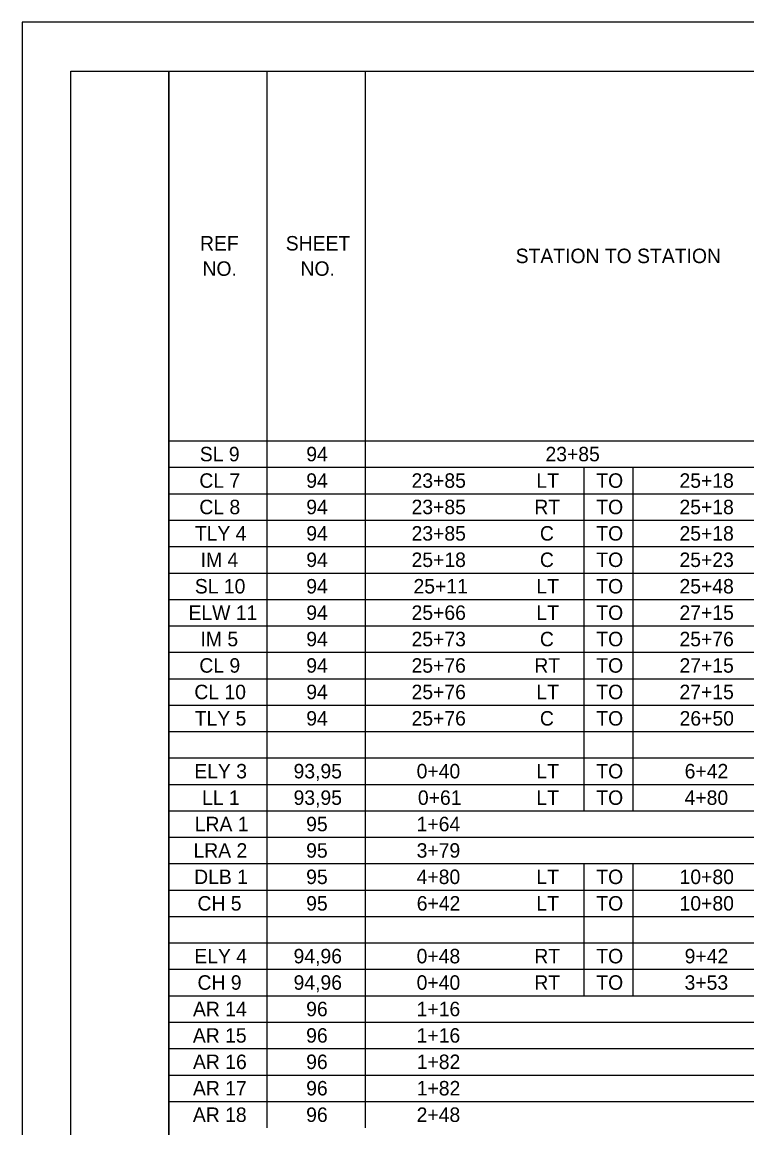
# Model space of a CAD drawing. Extents: x 0 to 34, y 0 to 22.
# Drawn here: x 0 to 7.41, y 10.69 to 22 of the extents above; entities that cross this region are included whole.
import ezdxf

# ---------------------------------------------------------------- set-up
doc = ezdxf.new("R2010")
doc.units = 0
for name, color, linetype in [('SH_Border', 7, 'Continuous'), ('SH_Cut_Line', 7, 'Continuous'), ('SH_Data', 7, 'Continuous')]:
    doc.layers.add(name, color=color, linetype=linetype)

msp = doc.modelspace()

# ---------------------------------------------------------------- linework, layer by layer
at = {"layer": 'SH_Border'}
for points in [[(0.5, 21.5), (1.5, 21.5), (1.5, 0.5), (0.5, 0.5)], [(1.5, 21.5), (33.5, 21.5), (33.5, 0.5), (1.5, 0.5)]]:
    msp.add_lwpolyline(points, close=True, dxfattribs=at)
at = {"layer": 'SH_Cut_Line'}
msp.add_lwpolyline([(0, 0), (34, 0), (34, 22), (0, 22)], close=True, dxfattribs=at)
at = {"layer": 'SH_Data'}
for p, q in [((1.5, 21.5), (5.747, 21.5)), ((1.5, 21.5), (1.5, 21.23)), ((2.504, 21.5), (2.504, 21.23)), ((3.508, 21.5), (3.508, 21.23)), ((5.747, 21.5), (6.249, 21.5)), ((6.249, 21.5), (7.716, 21.5)), ((1.5, 21.23), (1.5, 20.96)), ((2.504, 21.23), (2.504, 20.96)), ((3.508, 21.23), (3.508, 20.96)), ((1.5, 20.96), (1.5, 20.69)), ((2.504, 20.96), (2.504, 20.69)), ((3.508, 20.96), (3.508, 20.69)), ((1.5, 20.69), (1.5, 20.419)), ((2.504, 20.69), (2.504, 20.419)), ((3.508, 20.69), (3.508, 20.419)), ((1.5, 20.419), (1.5, 20.149)), ((2.504, 20.419), (2.504, 20.149)), ((3.508, 20.419), (3.508, 20.149)), ((1.5, 20.149), (1.5, 19.879)), ((2.504, 20.149), (2.504, 19.879)), ((3.508, 20.149), (3.508, 19.879)), ((1.5, 19.879), (1.5, 19.609)), ((2.504, 19.879), (2.504, 19.609)), ((3.508, 19.879), (3.508, 19.609)), ((1.5, 19.609), (1.5, 19.338)), ((2.504, 19.609), (2.504, 19.338)), ((3.508, 19.609), (3.508, 19.338)), ((1.5, 19.338), (1.5, 19.068)), ((2.504, 19.338), (2.504, 19.068)), ((3.508, 19.338), (3.508, 19.068)), ((1.5, 19.068), (1.5, 18.798)), ((2.504, 19.068), (2.504, 18.798)), ((3.508, 19.068), (3.508, 18.798)), ((1.5, 18.798), (1.5, 18.528)), ((2.504, 18.798), (2.504, 18.528)), ((3.508, 18.798), (3.508, 18.528)), ((1.5, 18.528), (1.5, 18.257)), ((2.504, 18.528), (2.504, 18.257)), ((3.508, 18.528), (3.508, 18.257)), ((1.5, 18.257), (1.5, 17.987)), ((2.504, 18.257), (2.504, 17.987)), ((3.508, 18.257), (3.508, 17.987)), ((1.5, 17.987), (1.5, 17.717)), ((2.504, 17.987), (2.504, 17.717)), ((3.508, 17.987), (3.508, 17.717)), ((1.5, 17.717), (5.747, 17.717)), ((1.5, 17.717), (1.5, 17.447)), ((2.504, 17.717), (2.504, 17.447)), ((3.508, 17.717), (3.508, 17.447)), ((5.747, 17.717), (6.249, 17.717)), ((6.249, 17.717), (7.716, 17.717)), ((1.5, 17.447), (5.747, 17.447)), ((1.5, 17.447), (1.5, 17.176)), ((2.504, 17.447), (2.504, 17.176)), ((3.508, 17.447), (3.508, 17.176)), ((5.747, 17.447), (6.249, 17.447)), ((5.747, 17.447), (5.747, 17.176)), ((6.249, 17.447), (7.716, 17.447)), ((6.249, 17.447), (6.249, 17.176)), ((1.5, 17.176), (5.747, 17.176)), ((1.5, 17.176), (1.5, 16.906)), ((2.504, 17.176), (2.504, 16.906)), ((3.508, 17.176), (3.508, 16.906)), ((5.747, 17.176), (6.249, 17.176)), ((5.747, 17.176), (5.747, 16.906)), ((6.249, 17.176), (7.716, 17.176)), ((6.249, 17.176), (6.249, 16.906)), ((1.5, 16.906), (5.747, 16.906)), ((1.5, 16.906), (1.5, 16.636)), ((2.504, 16.906), (2.504, 16.636)), ((3.508, 16.906), (3.508, 16.636)), ((5.747, 16.906), (6.249, 16.906)), ((5.747, 16.906), (5.747, 16.636)), ((6.249, 16.906), (7.716, 16.906)), ((6.249, 16.906), (6.249, 16.636)), ((1.5, 16.636), (5.747, 16.636)), ((1.5, 16.636), (1.5, 16.365)), ((2.504, 16.636), (2.504, 16.365)), ((3.508, 16.636), (3.508, 16.365)), ((5.747, 16.636), (6.249, 16.636)), ((5.747, 16.636), (5.747, 16.365)), ((6.249, 16.636), (7.716, 16.636)), ((6.249, 16.636), (6.249, 16.365)), ((1.5, 16.365), (5.747, 16.365)), ((1.5, 16.365), (1.5, 16.095)), ((2.504, 16.365), (2.504, 16.095)), ((3.508, 16.365), (3.508, 16.095)), ((5.747, 16.365), (6.249, 16.365)), ((5.747, 16.365), (5.747, 16.095)), ((6.249, 16.365), (7.716, 16.365)), ((6.249, 16.365), (6.249, 16.095)), ((1.5, 16.095), (5.747, 16.095)), ((1.5, 16.095), (1.5, 15.825)), ((2.504, 16.095), (2.504, 15.825)), ((3.508, 16.095), (3.508, 15.825)), ((5.747, 16.095), (6.249, 16.095)), ((5.747, 16.095), (5.747, 15.825)), ((6.249, 16.095), (7.716, 16.095)), ((6.249, 16.095), (6.249, 15.825)), ((1.5, 15.825), (5.747, 15.825)), ((1.5, 15.825), (1.5, 15.555)), ((2.504, 15.825), (2.504, 15.555)), ((3.508, 15.825), (3.508, 15.555)), ((5.747, 15.825), (6.249, 15.825)), ((5.747, 15.825), (5.747, 15.555)), ((6.249, 15.825), (7.716, 15.825)), ((6.249, 15.825), (6.249, 15.555)), ((1.5, 15.555), (5.747, 15.555)), ((1.5, 15.555), (1.5, 15.284)), ((2.504, 15.555), (2.504, 15.284)), ((3.508, 15.555), (3.508, 15.284)), ((5.747, 15.555), (6.249, 15.555)), ((5.747, 15.555), (5.747, 15.284)), ((6.249, 15.555), (7.716, 15.555)), ((6.249, 15.555), (6.249, 15.284)), ((1.5, 15.284), (5.747, 15.284)), ((1.5, 15.284), (1.5, 15.014)), ((2.504, 15.284), (2.504, 15.014)), ((3.508, 15.284), (3.508, 15.014)), ((5.747, 15.284), (6.249, 15.284)), ((5.747, 15.284), (5.747, 15.014)), ((6.249, 15.284), (7.716, 15.284)), ((6.249, 15.284), (6.249, 15.014)), ((1.5, 15.014), (5.747, 15.014)), ((1.5, 15.014), (1.5, 14.744)), ((2.504, 15.014), (2.504, 14.744)), ((3.508, 15.014), (3.508, 14.744)), ((5.747, 15.014), (6.249, 15.014)), ((5.747, 15.014), (5.747, 14.744)), ((6.249, 15.014), (7.716, 15.014)), ((6.249, 15.014), (6.249, 14.744)), ((1.5, 14.744), (5.747, 14.744)), ((1.5, 14.744), (1.5, 14.474)), ((2.504, 14.744), (2.504, 14.474)), ((3.508, 14.744), (3.508, 14.474)), ((5.747, 14.744), (6.249, 14.744)), ((5.747, 14.744), (5.747, 14.474)), ((6.249, 14.744), (7.716, 14.744)), ((6.249, 14.744), (6.249, 14.474)), ((1.5, 14.474), (5.747, 14.474)), ((1.5, 14.474), (1.5, 14.203)), ((2.504, 14.474), (2.504, 14.203)), ((3.508, 14.474), (3.508, 14.203)), ((5.747, 14.474), (6.249, 14.474)), ((5.747, 14.474), (5.747, 14.203)), ((6.249, 14.474), (7.716, 14.474)), ((6.249, 14.474), (6.249, 14.203)), ((1.5, 14.203), (5.747, 14.203)), ((1.5, 14.203), (1.5, 13.933)), ((2.504, 14.203), (2.504, 13.933)), ((3.508, 14.203), (3.508, 13.933)), ((5.747, 14.203), (6.249, 14.203)), ((5.747, 14.203), (5.747, 13.933)), ((6.249, 14.203), (7.716, 14.203)), ((6.249, 14.203), (6.249, 13.933)), ((1.5, 13.933), (5.747, 13.933)), ((1.5, 13.933), (1.5, 13.663)), ((2.504, 13.933), (2.504, 13.663)), ((3.508, 13.933), (3.508, 13.663)), ((5.747, 13.933), (6.249, 13.933)), ((6.249, 13.933), (7.716, 13.933)), ((1.5, 13.663), (5.747, 13.663)), ((1.5, 13.663), (1.5, 13.393)), ((2.504, 13.663), (2.504, 13.393)), ((3.508, 13.663), (3.508, 13.393)), ((5.747, 13.663), (6.249, 13.663)), ((6.249, 13.663), (7.716, 13.663)), ((1.5, 13.393), (5.747, 13.393)), ((1.5, 13.393), (1.5, 13.122)), ((2.504, 13.393), (2.504, 13.122)), ((3.508, 13.393), (3.508, 13.122)), ((5.747, 13.393), (6.249, 13.393)), ((5.747, 13.393), (5.747, 13.122)), ((6.249, 13.393), (7.716, 13.393)), ((6.249, 13.393), (6.249, 13.122)), ((1.5, 13.122), (5.747, 13.122)), ((1.5, 13.122), (1.5, 12.852)), ((2.504, 13.122), (2.504, 12.852)), ((3.508, 13.122), (3.508, 12.852)), ((5.747, 13.122), (6.249, 13.122)), ((5.747, 13.122), (5.747, 12.852)), ((6.249, 13.122), (7.716, 13.122)), ((6.249, 13.122), (6.249, 12.852)), ((1.5, 12.852), (5.747, 12.852)), ((1.5, 12.852), (1.5, 12.582)), ((2.504, 12.852), (2.504, 12.582)), ((3.508, 12.852), (3.508, 12.582)), ((5.747, 12.852), (6.249, 12.852)), ((5.747, 12.852), (5.747, 12.582)), ((6.249, 12.852), (7.716, 12.852)), ((6.249, 12.852), (6.249, 12.582)), ((1.5, 12.582), (5.747, 12.582)), ((1.5, 12.582), (1.5, 12.312)), ((2.504, 12.582), (2.504, 12.312)), ((3.508, 12.582), (3.508, 12.312)), ((5.747, 12.582), (6.249, 12.582)), ((5.747, 12.582), (5.747, 12.312)), ((6.249, 12.582), (7.716, 12.582)), ((6.249, 12.582), (6.249, 12.312)), ((1.5, 12.312), (5.747, 12.312)), ((1.5, 12.312), (1.5, 12.041)), ((2.504, 12.312), (2.504, 12.041)), ((3.508, 12.312), (3.508, 12.041)), ((5.747, 12.312), (6.249, 12.312)), ((5.747, 12.312), (5.747, 12.041)), ((6.249, 12.312), (7.716, 12.312)), ((6.249, 12.312), (6.249, 12.041)), ((1.5, 12.041), (5.747, 12.041)), ((1.5, 12.041), (1.5, 11.771)), ((2.504, 12.041), (2.504, 11.771)), ((3.508, 12.041), (3.508, 11.771)), ((5.747, 12.041), (6.249, 12.041)), ((6.249, 12.041), (7.716, 12.041)), ((1.5, 11.771), (5.747, 11.771)), ((1.5, 11.771), (1.5, 11.501)), ((2.504, 11.771), (2.504, 11.501)), ((3.508, 11.771), (3.508, 11.501)), ((5.747, 11.771), (6.249, 11.771)), ((6.249, 11.771), (7.716, 11.771)), ((1.5, 11.501), (5.747, 11.501)), ((1.5, 11.501), (1.5, 11.231)), ((2.504, 11.501), (2.504, 11.231)), ((3.508, 11.501), (3.508, 11.231)), ((5.747, 11.501), (6.249, 11.501)), ((6.249, 11.501), (7.716, 11.501)), ((1.5, 11.231), (5.747, 11.231)), ((1.5, 11.231), (1.5, 10.96)), ((2.504, 11.231), (2.504, 10.96)), ((3.508, 11.231), (3.508, 10.96)), ((5.747, 11.231), (6.249, 11.231)), ((6.249, 11.231), (7.716, 11.231)), ((1.5, 10.96), (5.747, 10.96)), ((1.5, 10.96), (1.5, 10.69)), ((2.504, 10.96), (2.504, 10.69)), ((3.508, 10.96), (3.508, 10.69)), ((5.747, 10.96), (6.249, 10.96)), ((6.249, 10.96), (7.716, 10.96))]:
    msp.add_line(p, q, dxfattribs=at)

# ---------------------------------------------------------------- texts
for s, p in [('REF', (1.82, 19.664)), ('SHEET', (2.697, 19.664)), ('STATION TO STATION', (5.049, 19.535)), ('NO.', (1.845, 19.405)), ('NO.', (2.848, 19.405)), ('SL 9', (1.818, 17.508)), ('94', (2.907, 17.508)), ('23+85', (5.354, 17.508)), ('CL 7', (1.813, 17.237)), ('94', (2.907, 17.237)), ('23+85', (3.984, 17.237)), ('LT', (5.261, 17.237)), ('TO', (5.874, 17.237)), ('25+18', (6.725, 17.237)), ('CL 8', (1.813, 16.967)), ('94', (2.907, 16.967)), ('23+85', (3.984, 16.967)), ('RT', (5.24, 16.967)), ('TO', (5.874, 16.967)), ('25+18', (6.725, 16.967)), ('TLY 4', (1.767, 16.697)), ('94', (2.907, 16.697)), ('23+85', (3.984, 16.697)), ('C', (5.297, 16.697)), ('TO', (5.874, 16.697)), ('25+18', (6.725, 16.697)), ('IM 4', (1.826, 16.427)), ('94', (2.907, 16.427)), ('25+18', (3.984, 16.427)), ('C', (5.297, 16.427)), ('TO', (5.874, 16.427)), ('25+23', (6.725, 16.427)), ('SL 10', (1.767, 16.156)), ('94', (2.907, 16.156)), ('25+11', (4.004, 16.156)), ('LT', (5.261, 16.156)), ('TO', (5.874, 16.156)), ('25+48', (6.725, 16.156)), ('ELW 11', (1.702, 15.886)), ('94', (2.907, 15.886)), ('25+66', (3.984, 15.886)), ('LT', (5.261, 15.886)), ('TO', (5.874, 15.886)), ('27+15', (6.725, 15.886)), ('IM 5', (1.825, 15.616)), ('94', (2.907, 15.616)), ('25+73', (3.984, 15.616)), ('C', (5.297, 15.616)), ('TO', (5.874, 15.616)), ('25+76', (6.725, 15.616)), ('CL 9', (1.813, 15.346)), ('94', (2.907, 15.346)), ('25+76', (3.984, 15.346)), ('TO', (5.874, 15.346)), ('27+15', (6.725, 15.346)), ('RT', (5.24, 15.346)), ('CL 10', (1.762, 15.075)), ('94', (2.907, 15.075)), ('25+76', (3.984, 15.075)), ('LT', (5.261, 15.075)), ('TO', (5.874, 15.075)), ('27+15', (6.725, 15.075)), ('TLY 5', (1.766, 14.805)), ('94', (2.907, 14.805)), ('25+76', (3.984, 14.805)), ('C', (5.297, 14.805)), ('TO', (5.874, 14.805)), ('26+50', (6.726, 14.805)), ('ELY 3', (1.761, 14.265)), ('93,95', (2.777, 14.265)), ('0+40', (4.036, 14.265)), ('LT', (5.261, 14.265)), ('TO', (5.874, 14.265)), ('6+42', (6.778, 14.265)), ('LL 1', (1.841, 13.994)), ('93,95', (2.777, 13.994)), ('0+61', (4.049, 13.994)), ('LT', (5.261, 13.994)), ('TO', (5.874, 13.994)), ('4+80', (6.777, 13.994)), ('LRA 1', (1.766, 13.724)), ('95', (2.906, 13.724)), ('1+64', (4.036, 13.724)), ('LRA 2', (1.753, 13.454)), ('95', (2.906, 13.454)), ('3+79', (4.036, 13.454)), ('DLB 1', (1.76, 13.184)), ('95', (2.906, 13.184)), ('4+80', (4.036, 13.184)), ('LT', (5.261, 13.184)), ('TO', (5.874, 13.184)), ('10+80', (6.726, 13.184)), ('CH 5', (1.794, 12.913)), ('95', (2.906, 12.913)), ('6+42', (4.037, 12.913)), ('LT', (5.261, 12.913)), ('TO', (5.874, 12.913)), ('10+80', (6.726, 12.913)), ('ELY 4', (1.762, 12.373)), ('94,96', (2.777, 12.373)), ('0+48', (4.036, 12.373)), ('RT', (5.24, 12.373)), ('TO', (5.874, 12.373)), ('9+42', (6.778, 12.373)), ('CH 9', (1.794, 12.103)), ('94,96', (2.777, 12.103)), ('0+40', (4.036, 12.103)), ('RT', (5.24, 12.103)), ('TO', (5.874, 12.103)), ('3+53', (6.777, 12.103)), ('AR 14', (1.748, 11.832)), ('96', (2.906, 11.832)), ('1+16', (4.036, 11.832)), ('AR 15', (1.747, 11.562)), ('96', (2.906, 11.562)), ('1+16', (4.036, 11.562)), ('AR 16', (1.748, 11.292)), ('96', (2.906, 11.292)), ('1+82', (4.037, 11.292)), ('AR 17', (1.748, 11.022)), ('96', (2.906, 11.022)), ('1+82', (4.037, 11.022)), ('AR 18', (1.747, 10.751)), ('96', (2.906, 10.751)), ('2+48', (4.036, 10.751))]:
    msp.add_text(s, height=0.148, dxfattribs=at).set_placement(p)

doc.saveas('drawing.dxf')
